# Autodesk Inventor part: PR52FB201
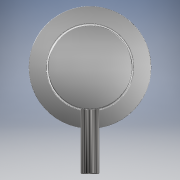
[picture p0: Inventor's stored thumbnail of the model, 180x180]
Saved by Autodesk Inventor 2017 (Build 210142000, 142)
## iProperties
Created: 2021-04
Part Number: PR52FB201
Material: Generico
Document SubType Name: Modeling
Designer: PIZZERA
Density: 1 g/cm^3
Appearance: Default
Author: PIZZERA
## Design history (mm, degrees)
feature "Base3"
node "Solido1"
node "Solido4"
